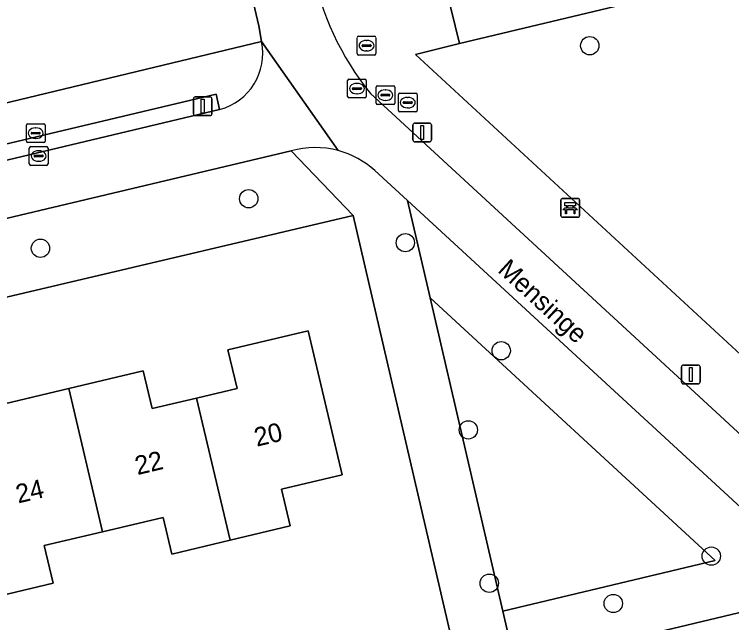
# Model space of a CAD drawing. Extents: x 158031 to 159244, y 380104 to 381214.
# Drawn here: x 158685.04 to 158723.36, y 380638.41 to 380670.9 of the extents above; entities that cross this region are included whole.
import ezdxf

# ---------------------------------------------------------------- set-up
doc = ezdxf.new("R2010")
doc.units = 0
for name, color, linetype in [('IMGEO_Bank', 7, 'Continuous'), ('IMGEO_Boom', 7, 'Continuous'), ('IMGEO_Erf', 7, 'Continuous'), ('IMGEO_Fietspad_open', 7, 'Continuous'), ('IMGEO_Groenvoorziening', 7, 'Continuous'), ('IMGEO_Hek', 7, 'Continuous'), ('IMGEO_Kolk', 7, 'Continuous'), ('IMGEO_Lichtmast', 7, 'Continuous'), ('IMGEO_Openbare_ruimte_label', 7, 'Continuous'), ('IMGEO_Pand', 7, 'Continuous'), ('IMGEO_Pand_nummerreeks', 7, 'Continuous'), ('IMGEO_Rijbaan_lokaal_open', 7, 'Continuous'), ('IMGEO_Rioolput', 7, 'Continuous'), ('IMGEO_Verkeerseiland_open', 7, 'Continuous'), ('IMGEO_Voetpad_open', 7, 'Continuous')]:
    doc.layers.add(name, color=color, linetype=linetype)

msp = doc.modelspace()

# ---------------------------------------------------------------- linework, layer by layer
at = {"layer": 'IMGEO_Bank'}
for p, q in [((158714.236, 380660.135), (158714.236, 380660.976)), ((158714.236, 380660.976), (158714.236, 380660.135)), ((158714.311, 380661.06), (158715.152, 380661.06)), ((158715.152, 380661.06), (158714.311, 380661.06)), ((158715.236, 380660.985), (158715.236, 380660.144)), ((158715.236, 380660.144), (158715.236, 380660.985)), ((158714.545, 380660.566), (158714.545, 380660.672)), ((158714.589, 380660.672), (158714.589, 380660.566)), ((158714.877, 380660.678), (158714.595, 380660.678)), ((158714.595, 380660.56), (158714.877, 380660.56)), ((158714.883, 380660.566), (158714.883, 380660.672)), ((158714.927, 380660.672), (158714.927, 380660.566)), ((158714.933, 380660.458), (158714.54, 380660.458)), ((158715.161, 380660.06), (158714.32, 380660.06)), ((158714.32, 380660.06), (158715.161, 380660.06))]:
    msp.add_line(p, q, dxfattribs=at)
for points in [[(158714.483, 380660.458), (158714.341, 380660.458), (158714.453, 380660.56), (158714.539, 380660.56)], [(158714.539, 380660.678), (158714.453, 380660.678), (158714.453, 380660.839), (158715.016, 380660.839), (158715.016, 380660.678), (158714.933, 380660.678)], [(158714.933, 380660.56), (158715.016, 380660.56), (158715.128, 380660.458), (158714.989, 380660.458)], [(158714.533, 380660.451), (158714.533, 380660.244), (158714.49, 380660.244), (158714.49, 380660.451)], [(158714.983, 380660.451), (158714.983, 380660.244), (158714.939, 380660.244), (158714.939, 380660.451)]]:
    msp.add_lwpolyline(points, dxfattribs=at)
for centre, radius, start, end in [((158714.314, 380660.982), 0.0779, 92.4484, 184.2845), ((158714.314, 380660.982), 0.0779, 92.4484, 184.2845), ((158715.158, 380660.982), 0.0779, 2.4484, 94.2845), ((158715.158, 380660.982), 0.0779, 2.4484, 94.2845), ((158714.538, 380660.671), 0.00671, 2.8957, 87.1043), ((158714.538, 380660.567), 0.00671, 272.8957, 357.1043), ((158714.595, 380660.671), 0.00671, 92.8957, 177.1043), ((158714.595, 380660.567), 0.00671, 182.8957, 267.1043), ((158714.877, 380660.671), 0.00671, 2.8957, 87.1043), ((158714.877, 380660.567), 0.00671, 272.8957, 357.1043), ((158714.934, 380660.671), 0.00671, 92.8957, 177.1043), ((158714.934, 380660.567), 0.00671, 182.8957, 267.1043), ((158714.314, 380660.138), 0.0779, 182.4484, 274.2845), ((158714.314, 380660.138), 0.0779, 182.4484, 274.2845), ((158714.483, 380660.451), 0.00671, 2.8957, 87.1043), ((158714.54, 380660.451), 0.00671, 92.8957, 177.1043), ((158714.932, 380660.451), 0.00671, 2.8957, 87.1043), ((158714.989, 380660.451), 0.00671, 92.8957, 177.1043), ((158715.158, 380660.138), 0.0779, 272.4484, 4.2845), ((158715.158, 380660.138), 0.0779, 272.4484, 4.2845)]:
    msp.add_arc(centre, radius, start, end, dxfattribs=at)
at = {"layer": 'IMGEO_Boom'}
for centre in [(158715.778, 380669.222), (158697.564, 380661.049), (158705.926, 380658.701), (158686.439, 380658.405), (158711.047, 380652.931), (158709.29, 380648.704), (158722.268, 380641.96), (158710.409, 380640.513), (158717.032, 380639.431)]:
    msp.add_circle(centre, 0.489, dxfattribs=at)
at = {"layer": 'IMGEO_Erf'}
msp.add_lwpolyline([(158686.881, 380718.056), (158686.652, 380719.032), (158670.862, 380715.31), (158649.457, 380710.132), (158646.034, 380709.321), (158573.471, 380692.129), (158581.882, 380657.767), (158585.545, 380642.697), (158606.222, 380647.594), (158605.611, 380650.592), (158645.531, 380659.999), (158646.233, 380657.02), (158679.017, 380664.973), (158679.063, 380664.833), (158698.247, 380669.444), (158698.093, 380670.277)], close=True, dxfattribs=at)
for points in [[(158748.582, 380678.823), (158708.828, 380669.343), (158706.466, 380668.758), (158730.316, 380646.742)], [(158683.991, 380629.458), (158688.336, 380630.486), (158687.692, 380633.211), (158691.868, 380634.198), (158696.043, 380635.184), (158696.687, 380632.459), (158701.037, 380633.499), (158700.391, 380636.223), (158704.695, 380637.244), (158705.341, 380634.52), (158708.805, 380635.392), (158708.736, 380635.684), (158708.827, 380635.706), (158703.146, 380660.152), (158636.227, 380644.398)], [(158683.757, 380649.92), (158687.949, 380650.914), (158691.925, 380651.856), (158692.402, 380649.841), (158694.768, 380650.402), (158696.939, 380650.916), (158696.451, 380652.979), (158700.735, 380653.994), (158702.558, 380646.298), (158699.319, 380645.53), (158699.783, 380643.571), (158696.563, 380642.808), (158693.453, 380642.071), (158692.989, 380644.028), (158689.757, 380643.262), (158686.641, 380642.524), (158687.116, 380640.519), (158683.888, 380639.754)]]:
    msp.add_lwpolyline(points, dxfattribs=at)
at = {"layer": 'IMGEO_Fietspad_open'}
for points in [[(158700.954, 380673.41), (158700.79, 380674.108), (158690.475, 380718.05), (158688.969, 380724.462), (158685.569, 380723.649), (158686.652, 380719.032), (158686.881, 380718.056), (158698.093, 380670.277), (158698.247, 380669.444), (158702.34, 380663.618)], [(158702.34, 380663.618), (158698.247, 380669.444)], [(158728.229, 380644.402), (158704.073, 380666.661)], [(158696.009, 380665.807), (158643.138, 380653.223), (158629.34, 380649.935), (158627.43, 380649.482), (158614.401, 380646.377), (158579.653, 380638.172), (158540.516, 380628.901), (158516.204, 380623.141), (158513.405, 380622.477), (158513.999, 380619.504), (158577.006, 380634.495), (158580.413, 380635.282), (158623.804, 380645.539), (158625.123, 380645.847), (158627.976, 380646.522), (158630.034, 380647.004), (158632.592, 380647.598), (158637.143, 380648.746), (158637.266, 380648.766), (158699.836, 380663.612)], [(158704.299, 380662.558), (158706.04, 380660.954), (158725.661, 380642.88)]]:
    msp.add_lwpolyline(points, dxfattribs=at)
for centre, radius, start, end in [((158715.749, 380676.152), 15.047, 190.5, 219.1074), ((158695.188, 380668.819), 3.122, 285.2468, 11.5417), ((158701.099, 380658.977), 4.804, 75.032, 105.2426), ((158701.096, 380658.978), 4.804, 48.1767, 74.9883)]:
    msp.add_arc(centre, radius, start, end, dxfattribs=at)
at = {"layer": 'IMGEO_Groenvoorziening'}
for points in [[(158635.745, 380646.353), (158636.227, 380644.398), (158703.146, 380660.152), (158699.836, 380663.612), (158637.266, 380648.766)], [(158699.836, 380663.612), (158703.146, 380660.152), (158708.827, 380635.706), (158711.747, 380636.397), (158711.136, 380639.023), (158707.246, 380655.764), (158706.04, 380660.954), (158704.299, 380662.558)], [(158725.661, 380642.88), (158706.04, 380660.954), (158707.246, 380655.764), (158722.483, 380641.728), (158711.136, 380639.023), (158711.747, 380636.397), (158714.693, 380637.095), (158714.762, 380636.803), (158727.607, 380639.865)]]:
    msp.add_lwpolyline(points, dxfattribs=at)
msp.add_lwpolyline([(158707.246, 380655.764), (158711.136, 380639.023), (158722.483, 380641.728)], close=True, dxfattribs=at)
for centre, start, end in [((158701.099, 380658.977), 75.032, 105.2426), ((158701.096, 380658.978), 48.1767, 74.9883)]:
    msp.add_arc(centre, 4.804, start, end, dxfattribs=at)
at = {"layer": 'IMGEO_Hek'}
for points in [[(158698.093, 380670.277), (158686.881, 380718.056)], [(158698.247, 380669.444), (158698.093, 380670.277)], [(158698.247, 380669.444), (158679.063, 380664.833), (158679.017, 380664.973), (158646.233, 380657.02), (158645.531, 380659.999), (158605.611, 380650.592), (158606.222, 380647.594), (158585.545, 380642.697), (158581.882, 380657.767)]]:
    msp.add_lwpolyline(points, dxfattribs=at)
at = {"layer": 'IMGEO_Kolk'}
for p, q in [((158685.684, 380664.125), (158685.684, 380664.977)), ((158685.759, 380665.051), (158686.611, 380665.051)), ((158686.172, 380664.831), (158686.197, 380664.831)), ((158686.685, 380664.977), (158686.685, 380664.125)), ((158685.943, 380664.545), (158685.943, 380664.557)), ((158686.381, 380664.508), (158685.983, 380664.508)), ((158685.986, 380664.594), (158686.384, 380664.594)), ((158686.427, 380664.557), (158686.427, 380664.545)), ((158686.611, 380664.051), (158685.759, 380664.051)), ((158686.195, 380664.271), (158686.17, 380664.271)), ((158685.842, 380662.905), (158685.842, 380663.757)), ((158685.917, 380663.831), (158686.769, 380663.831)), ((158686.33, 380663.611), (158686.355, 380663.611)), ((158686.843, 380663.757), (158686.843, 380662.905)), ((158686.101, 380663.325), (158686.101, 380663.337)), ((158686.539, 380663.288), (158686.141, 380663.288)), ((158686.144, 380663.374), (158686.542, 380663.374)), ((158686.585, 380663.337), (158686.585, 380663.325)), ((158686.769, 380662.831), (158685.917, 380662.831)), ((158686.353, 380663.051), (158686.328, 380663.051))]:
    msp.add_line(p, q, dxfattribs=at)
for points in [[(158685.684, 380664.125), (158685.684, 380664.977)], [(158685.759, 380665.051), (158686.611, 380665.051)], [(158686.685, 380664.977), (158686.685, 380664.125)], [(158686.611, 380664.051), (158685.759, 380664.051)], [(158685.842, 380662.905), (158685.842, 380663.757)], [(158685.917, 380663.831), (158686.769, 380663.831)], [(158686.843, 380663.757), (158686.843, 380662.905)], [(158686.769, 380662.831), (158685.917, 380662.831)]]:
    msp.add_lwpolyline(points, dxfattribs=at)
for centre, radius, start, end in [((158685.761, 380664.975), 0.0765, 91.552, 178.448), ((158685.761, 380664.975), 0.0765, 91.552, 178.448), ((158686.609, 380664.975), 0.0765, 1.552, 88.448), ((158686.609, 380664.975), 0.0765, 1.552, 88.448), ((158685.983, 380664.554), 0.0403, 85.8775, 175.7526), ((158685.98, 380664.544), 0.0366, 178.938, 274.7102), ((158686.384, 380664.551), 0.043, 264.8664, 352.4533), ((158686.388, 380664.556), 0.0386, 1.7309, 96.639), ((158685.761, 380664.127), 0.0765, 181.552, 268.448), ((158685.761, 380664.127), 0.0765, 181.552, 268.448), ((158686.609, 380664.127), 0.0765, 271.552, 358.448), ((158686.609, 380664.127), 0.0765, 271.552, 358.448), ((158685.919, 380663.755), 0.0765, 91.552, 178.448), ((158685.919, 380663.755), 0.0765, 91.552, 178.448), ((158686.767, 380663.755), 0.0765, 1.552, 88.448), ((158686.767, 380663.755), 0.0765, 1.552, 88.448), ((158686.141, 380663.334), 0.0403, 85.8775, 175.7526), ((158686.138, 380663.324), 0.0366, 178.938, 274.7102), ((158686.542, 380663.331), 0.043, 264.8664, 352.4533), ((158686.546, 380663.336), 0.0386, 1.7309, 96.639), ((158685.919, 380662.907), 0.0765, 181.552, 268.448), ((158685.919, 380662.907), 0.0765, 181.552, 268.448), ((158686.767, 380662.907), 0.0765, 271.552, 358.448), ((158686.767, 380662.907), 0.0765, 271.552, 358.448)]:
    msp.add_arc(centre, radius, start, end, dxfattribs=at)
for centre, major_axis, ratio, start_param, end_param in [((158686.171, 380664.551), (-0.387, 0.002), 0.722429, 4.712389, 7.853982), ((158686.196, 380664.551), (-0.39, 0.002), 0.717154, 1.570796, 4.712389), ((158686.329, 380663.331), (-0.387, 0.002), 0.722429, 4.712389, 7.853982), ((158686.354, 380663.331), (-0.39, 0.002), 0.717154, 1.570796, 4.712389)]:
    msp.add_ellipse(centre, major_axis=major_axis, ratio=ratio, start_param=start_param, end_param=end_param, dxfattribs=at)
at = {"layer": 'IMGEO_Lichtmast'}
for p, q in [((158694.608, 380665.589), (158694.608, 380666.389)), ((158694.608, 380666.389), (158694.608, 380665.589)), ((158694.708, 380666.489), (158695.498, 380666.489)), ((158695.498, 380666.489), (158694.708, 380666.489)), ((158695.598, 380666.389), (158695.598, 380665.589)), ((158695.598, 380665.589), (158695.598, 380666.389)), ((158695.498, 380665.489), (158694.708, 380665.489)), ((158694.708, 380665.489), (158695.498, 380665.489)), ((158706.431, 380665.087), (158707.221, 380665.087)), ((158707.221, 380665.087), (158706.431, 380665.087)), ((158706.331, 380664.187), (158706.331, 380664.987)), ((158706.331, 380664.987), (158706.331, 380664.187)), ((158707.321, 380664.987), (158707.321, 380664.187)), ((158707.321, 380664.187), (158707.321, 380664.987)), ((158707.221, 380664.087), (158706.431, 380664.087)), ((158706.431, 380664.087), (158707.221, 380664.087)), ((158720.677, 380651.264), (158720.677, 380652.064)), ((158720.677, 380652.064), (158720.677, 380651.264)), ((158720.777, 380652.164), (158721.567, 380652.164)), ((158721.567, 380652.164), (158720.777, 380652.164)), ((158721.667, 380652.064), (158721.667, 380651.264)), ((158721.667, 380651.264), (158721.667, 380652.064)), ((158721.567, 380651.164), (158720.777, 380651.164)), ((158720.777, 380651.164), (158721.567, 380651.164))]:
    msp.add_line(p, q, dxfattribs=at)
for points in [[(158695.028, 380666.364), (158695.178, 380666.364), (158695.178, 380665.614), (158695.028, 380665.614), (158695.028, 380666.364)], [(158706.751, 380664.962), (158706.901, 380664.962), (158706.901, 380664.212), (158706.751, 380664.212), (158706.751, 380664.962)], [(158721.097, 380652.039), (158721.247, 380652.039), (158721.247, 380651.289), (158721.097, 380651.289), (158721.097, 380652.039)]]:
    msp.add_lwpolyline(points, dxfattribs=at)
for centre, start, end in [((158694.708, 380666.389), 90, 180), ((158694.708, 380666.389), 90, 180), ((158695.498, 380666.389), 0, 90), ((158695.498, 380666.389), 360, 90), ((158694.708, 380665.589), 180, 270), ((158694.708, 380665.589), 180, 270), ((158695.498, 380665.589), 270, 0), ((158695.498, 380665.589), 270, 0), ((158706.431, 380664.987), 90, 180), ((158706.431, 380664.987), 90, 180), ((158707.221, 380664.987), 0, 90), ((158707.221, 380664.987), 360, 90), ((158706.431, 380664.187), 180, 270), ((158706.431, 380664.187), 180, 270), ((158707.221, 380664.187), 270, 0), ((158707.221, 380664.187), 270, 0), ((158720.777, 380652.064), 90, 180), ((158720.777, 380652.064), 90, 180), ((158721.567, 380652.064), 0, 90), ((158721.567, 380652.064), 360, 90), ((158720.777, 380651.264), 180, 270), ((158720.777, 380651.264), 180, 270), ((158721.567, 380651.264), 270, 0), ((158721.567, 380651.264), 270, 0)]:
    msp.add_arc(centre, 0.1, start, end, dxfattribs=at)
at = {"layer": 'IMGEO_Pand'}
for points in [[(158696.563, 380642.808), (158699.783, 380643.571), (158699.319, 380645.53), (158702.558, 380646.298), (158700.735, 380653.994), (158696.451, 380652.979), (158696.939, 380650.916), (158694.768, 380650.402)], [(158696.563, 380642.808), (158694.768, 380650.402), (158692.402, 380649.841), (158691.925, 380651.856), (158687.949, 380650.914), (158689.757, 380643.262), (158692.989, 380644.028), (158693.453, 380642.071)], [(158682.071, 380647.442), (158683.888, 380639.754), (158687.116, 380640.519), (158686.641, 380642.524), (158689.757, 380643.262), (158687.949, 380650.914), (158683.757, 380649.92), (158684.223, 380647.952)]]:
    msp.add_lwpolyline(points, close=True, dxfattribs=at)
at = {"layer": 'IMGEO_Rijbaan_lokaal_open'}
msp.add_lwpolyline([(158750.174, 380679.208), (158766.488, 380683.072), (158767.9, 380683.248), (158765.89, 380686.863), (158753.961, 380683.898), (158753.673, 380685.02), (158743.41, 380682.598), (158743.676, 380681.511), (158734.975, 380679.444), (158734.715, 380680.524), (158726.673, 380678.622), (158726.39, 380679.673), (158723.65, 380679.014), (158720.923, 380678.358), (158718.197, 380677.702), (158715.471, 380677.046), (158712.744, 380676.389), (158710.018, 380675.733), (158707.267, 380675.071), (158707.432, 380675.011), (158708.828, 380669.343), (158748.582, 380678.823)], close=True, dxfattribs=at)
at = {"layer": 'IMGEO_Rioolput'}
for p, q in [((158703.43, 380669.725), (158704.282, 380669.725)), ((158703.355, 380668.799), (158703.355, 380669.651)), ((158703.843, 380669.505), (158703.868, 380669.505)), ((158704.356, 380669.651), (158704.356, 380668.799)), ((158703.614, 380669.219), (158703.614, 380669.231)), ((158704.052, 380669.182), (158703.654, 380669.182)), ((158703.657, 380669.268), (158704.055, 380669.268)), ((158703.866, 380668.945), (158703.841, 380668.945)), ((158704.098, 380669.231), (158704.098, 380669.219)), ((158704.282, 380668.725), (158703.43, 380668.725)), ((158702.917, 380667.431), (158703.769, 380667.431)), ((158702.842, 380666.505), (158702.842, 380667.357)), ((158703.33, 380667.211), (158703.355, 380667.211)), ((158703.843, 380667.357), (158703.843, 380666.505)), ((158704.36, 380666.156), (158704.36, 380667.008)), ((158704.435, 380667.082), (158705.287, 380667.082)), ((158705.361, 380667.008), (158705.361, 380666.156)), ((158703.101, 380666.925), (158703.101, 380666.937)), ((158703.539, 380666.888), (158703.141, 380666.888)), ((158703.144, 380666.974), (158703.542, 380666.974)), ((158703.353, 380666.651), (158703.328, 380666.651)), ((158703.585, 380666.937), (158703.585, 380666.925)), ((158704.662, 380666.625), (158705.06, 380666.625)), ((158704.848, 380666.862), (158704.873, 380666.862)), ((158705.631, 380666.683), (158706.483, 380666.683)), ((158703.769, 380666.431), (158702.917, 380666.431)), ((158704.619, 380666.576), (158704.619, 380666.588)), ((158705.057, 380666.539), (158704.659, 380666.539)), ((158704.871, 380666.302), (158704.846, 380666.302)), ((158705.103, 380666.588), (158705.103, 380666.576)), ((158705.556, 380665.757), (158705.556, 380666.609)), ((158706.044, 380666.463), (158706.069, 380666.463)), ((158706.557, 380666.609), (158706.557, 380665.757)), ((158705.287, 380666.082), (158704.435, 380666.082)), ((158705.815, 380666.177), (158705.815, 380666.189)), ((158706.253, 380666.14), (158705.855, 380666.14)), ((158705.858, 380666.226), (158706.256, 380666.226)), ((158706.067, 380665.903), (158706.042, 380665.903)), ((158706.299, 380666.189), (158706.299, 380666.177)), ((158706.483, 380665.683), (158705.631, 380665.683))]:
    msp.add_line(p, q, dxfattribs=at)
for points in [[(158703.43, 380669.725), (158704.282, 380669.725)], [(158703.355, 380668.799), (158703.355, 380669.651)], [(158704.356, 380669.651), (158704.356, 380668.799)], [(158704.282, 380668.725), (158703.43, 380668.725)], [(158702.917, 380667.431), (158703.769, 380667.431)], [(158702.842, 380666.505), (158702.842, 380667.357)], [(158703.843, 380667.357), (158703.843, 380666.505)], [(158704.36, 380666.156), (158704.36, 380667.008)], [(158704.435, 380667.082), (158705.287, 380667.082)], [(158705.361, 380667.008), (158705.361, 380666.156)], [(158705.631, 380666.683), (158706.483, 380666.683)], [(158703.769, 380666.431), (158702.917, 380666.431)], [(158705.556, 380665.757), (158705.556, 380666.609)], [(158706.557, 380666.609), (158706.557, 380665.757)], [(158705.287, 380666.082), (158704.435, 380666.082)], [(158706.483, 380665.683), (158705.631, 380665.683)]]:
    msp.add_lwpolyline(points, dxfattribs=at)
for centre, radius, start, end in [((158703.432, 380669.649), 0.0765, 91.552, 178.448), ((158703.432, 380669.649), 0.0765, 91.552, 178.448), ((158704.28, 380669.649), 0.0765, 1.552, 88.448), ((158704.28, 380669.649), 0.0765, 1.552, 88.448), ((158703.654, 380669.228), 0.0403, 85.8775, 175.7526), ((158703.651, 380669.218), 0.0366, 178.938, 274.7102), ((158704.055, 380669.225), 0.043, 264.8664, 352.4533), ((158704.059, 380669.23), 0.0386, 1.7309, 96.639), ((158703.432, 380668.801), 0.0765, 181.552, 268.448), ((158703.432, 380668.801), 0.0765, 181.552, 268.448), ((158704.28, 380668.801), 0.0765, 271.552, 358.448), ((158704.28, 380668.801), 0.0765, 271.552, 358.448), ((158702.919, 380667.355), 0.0765, 91.552, 178.448), ((158702.919, 380667.355), 0.0765, 91.552, 178.448), ((158703.767, 380667.355), 0.0765, 1.552, 88.448), ((158703.767, 380667.355), 0.0765, 1.552, 88.448), ((158704.437, 380667.006), 0.0765, 91.552, 178.448), ((158704.437, 380667.006), 0.0765, 91.552, 178.448), ((158705.285, 380667.006), 0.0765, 1.552, 88.448), ((158705.285, 380667.006), 0.0765, 1.552, 88.448), ((158703.141, 380666.934), 0.0403, 85.8775, 175.7526), ((158703.138, 380666.924), 0.0366, 178.938, 274.7102), ((158703.542, 380666.931), 0.043, 264.8664, 352.4533), ((158703.546, 380666.936), 0.0386, 1.7309, 96.639), ((158704.659, 380666.585), 0.0403, 85.8775, 175.7526), ((158705.064, 380666.587), 0.0386, 1.7309, 96.639), ((158705.633, 380666.607), 0.0765, 91.552, 178.448), ((158705.633, 380666.607), 0.0765, 91.552, 178.448), ((158706.481, 380666.607), 0.0765, 1.552, 88.448), ((158706.481, 380666.607), 0.0765, 1.552, 88.448), ((158702.919, 380666.507), 0.0765, 181.552, 268.448), ((158702.919, 380666.507), 0.0765, 181.552, 268.448), ((158703.767, 380666.507), 0.0765, 271.552, 358.448), ((158703.767, 380666.507), 0.0765, 271.552, 358.448), ((158704.656, 380666.575), 0.0366, 178.938, 274.7102), ((158705.06, 380666.582), 0.043, 264.8664, 352.4533), ((158704.437, 380666.158), 0.0765, 181.552, 268.448), ((158704.437, 380666.158), 0.0765, 181.552, 268.448), ((158705.285, 380666.158), 0.0765, 271.552, 358.448), ((158705.285, 380666.158), 0.0765, 271.552, 358.448), ((158705.855, 380666.186), 0.0403, 85.8775, 175.7526), ((158705.852, 380666.176), 0.0366, 178.938, 274.7102), ((158706.256, 380666.183), 0.043, 264.8664, 352.4533), ((158706.26, 380666.188), 0.0386, 1.7309, 96.639), ((158705.633, 380665.759), 0.0765, 181.552, 268.448), ((158705.633, 380665.759), 0.0765, 181.552, 268.448), ((158706.481, 380665.759), 0.0765, 271.552, 358.448), ((158706.481, 380665.759), 0.0765, 271.552, 358.448)]:
    msp.add_arc(centre, radius, start, end, dxfattribs=at)
for centre, major_axis, ratio, start_param, end_param in [((158703.842, 380669.225), (-0.387, 0.002), 0.722429, 4.712389, 7.853982), ((158703.867, 380669.225), (-0.39, 0.002), 0.717154, 1.570796, 4.712389), ((158703.329, 380666.931), (-0.387, 0.002), 0.722429, 4.712389, 7.853982), ((158703.354, 380666.931), (-0.39, 0.002), 0.717154, 1.570796, 4.712389), ((158704.847, 380666.582), (-0.387, 0.002), 0.722429, 4.712389, 7.853982), ((158704.872, 380666.582), (-0.39, 0.002), 0.717154, 1.570796, 4.712389), ((158706.043, 380666.183), (-0.387, 0.002), 0.722429, 4.712389, 7.853982), ((158706.068, 380666.183), (-0.39, 0.002), 0.717154, 1.570796, 4.712389)]:
    msp.add_ellipse(centre, major_axis=major_axis, ratio=ratio, start_param=start_param, end_param=end_param, dxfattribs=at)
at = {"layer": 'IMGEO_Verkeerseiland_open'}
msp.add_lwpolyline([(158696.009, 380665.807), (158695.817, 380666.633), (158642.266, 380653.921), (158643.138, 380653.223)], close=True, dxfattribs=at)
at = {"layer": 'IMGEO_Voetpad_open'}
for points in [[(158730.316, 380646.742), (158706.466, 380668.758), (158708.828, 380669.343), (158707.432, 380675.011)], [(158698.247, 380669.444), (158679.063, 380664.833), (158679.017, 380664.973), (158646.233, 380657.02), (158645.531, 380659.999), (158605.611, 380650.592), (158606.222, 380647.594), (158585.545, 380642.697), (158582.005, 380641.477), (158579.059, 380640.785), (158579.128, 380640.493), (158578.836, 380640.425), (158579.03, 380639.698), (158578.235, 380639.51), (158560.791, 380635.377), (158560.659, 380635.948), (158557.728, 380635.248)], [(158540.301, 380629.746), (158540.516, 380628.901), (158579.653, 380638.172), (158579.452, 380638.994), (158614.173, 380647.222), (158614.074, 380647.672), (158615.39, 380650.312), (158626.635, 380652.977), (158627.43, 380649.482), (158629.34, 380649.935), (158628.532, 380653.422), (158639.496, 380656.032), (158642.266, 380653.921), (158695.817, 380666.633), (158696.009, 380665.807)], [(158704.073, 380666.661), (158728.229, 380644.402)]]:
    msp.add_lwpolyline(points, dxfattribs=at)
msp.add_lwpolyline([(158727.607, 380639.865), (158714.762, 380636.803), (158715.598, 380633.518), (158722.624, 380635.163), (158725.401, 380635.761), (158726.416, 380631.538), (158726.679, 380630.339), (158727.683, 380626.11), (158732.222, 380606.886), (158733.22, 380602.635), (158733.51, 380601.433), (158734.47, 380597.31), (158735.431, 380593.188), (158735.725, 380591.97), (158736.726, 380587.734), (158739.029, 380577.884), (158742.026, 380578.534), (158741.77, 380579.626)], close=True, dxfattribs=at)
for centre, radius, start, end in [((158715.749, 380676.152), 15.047, 190.5, 219.1074), ((158695.188, 380668.819), 3.122, 285.2468, 11.5417)]:
    msp.add_arc(centre, radius, start, end, dxfattribs=at)

# ---------------------------------------------------------------- texts
at = {"layer": 'IMGEO_Openbare_ruimte_label'}
msp.add_text('Mensinge', height=1, rotation=317.391, dxfattribs=at).set_placement((158710.808, 380657.178))
at = {"layer": 'IMGEO_Pand_nummerreeks'}
for s, p in [('20', (158697.99, 380647.802)), ('22', (158691.618, 380646.286)), ('24', (158685.252, 380644.772))]:
    msp.add_text(s, height=1, rotation=13.379, dxfattribs=at).set_placement(p)

doc.saveas('drawing.dxf')
